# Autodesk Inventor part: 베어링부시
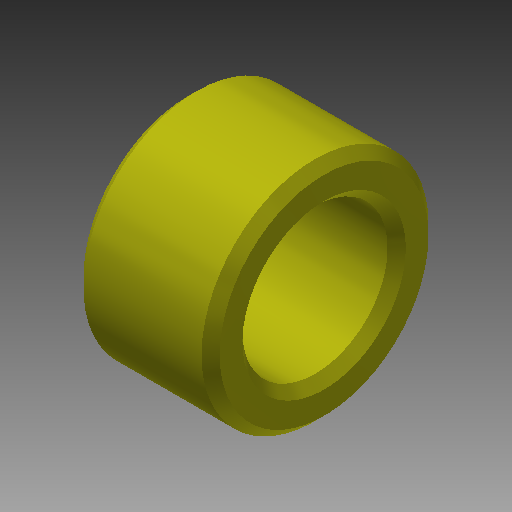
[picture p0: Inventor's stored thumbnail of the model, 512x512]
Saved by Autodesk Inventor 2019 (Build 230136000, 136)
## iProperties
Created: 2019-03
Part Number: 베어링부시
Material: 강철, 연강
Document SubType Name: Modeling
Designer: mduedu
Density: 1 g/cm^3
Appearance: 노란색
Author: mduedu
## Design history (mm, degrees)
sketch "스케치1"
  geometry: L1 (-7.5, 12.5)-(7.5, 12.5); L2 (7.5, 12.5)-(7.5, 8); L3 (7.5, 8)-(-7.5, 8); L4 (-7.5, 8)-(-7.5, 12.5); L5 (-7.5, 0)-(7.5, 0); 3 further points
  constraints: 10 end point, 2 midpoint, 2 parallel, 2 perpendicular, 2 vertical alignment, 1 coincident, 1 horizontal
  dimensions: "d0" = 16 diameter of L3 L5; "d2" = 25 diameter of L1 L5; "d3" = 15 distance of L1.start L1.end
revolve "회전1" sketch "스케치1" stored, may be unused: angle "d4" = 90 deg
chamfer "모따기1" distance "d5" = 1; stored, may be unused: second distance "d6" = 2, angle "d7" = 45 deg
chamfer "모따기2" distance "d8" = 1; stored, may be unused: second distance "d9" = 2, angle "d10" = 45 deg
node "솔리드1"
